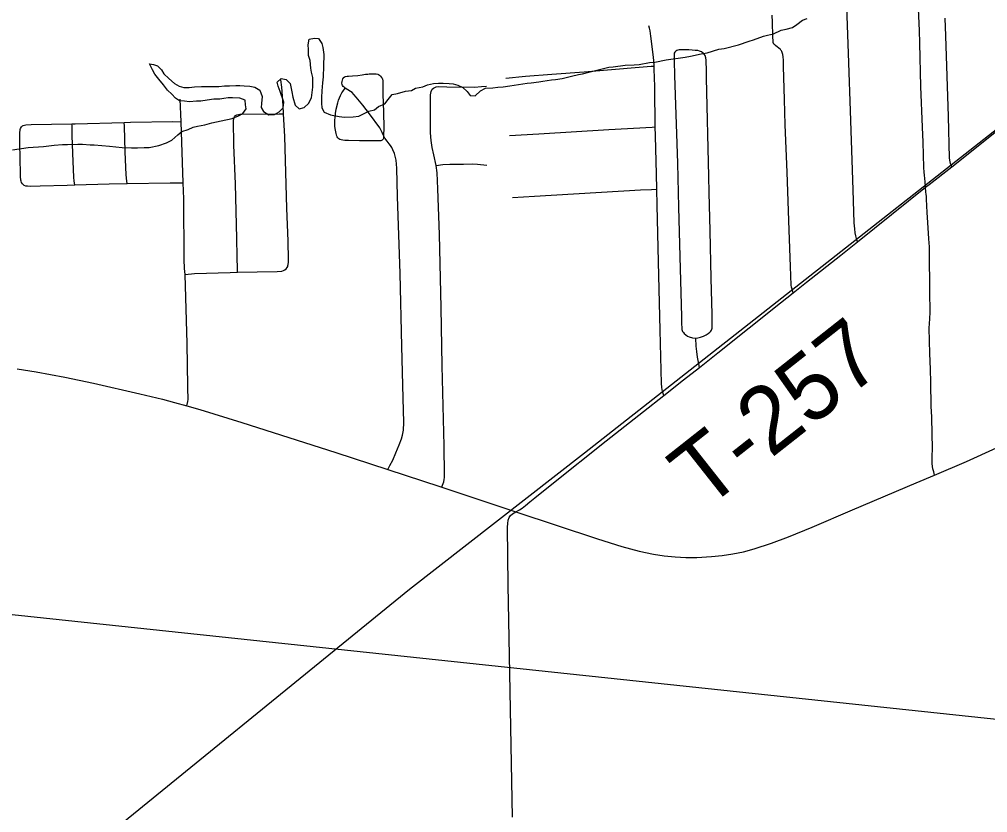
# Model space of a CAD drawing. Extents: x 63.4 to 97.4, y 0.4 to 22.4.
# Drawn here: x 71.177 to 72.001, y 17.297 to 17.973 of the extents above; entities that cross this region are included whole.
import ezdxf

# ---------------------------------------------------------------- set-up
doc = ezdxf.new("R2010")
doc.units = 0
for name, color, linetype in [('GM_X_Minor_River', 7, 'Continuous'), ('GM_X_Rail_Line', 7, 'Continuous'), ('GM_X_State_Route', 7, 'Continuous'), ('GM_X_Township_Road', 7, 'Continuous'), ('GM_X_Township_Road_Text', 7, 'Continuous'), ('SH_Data', 7, 'Continuous')]:
    doc.layers.add(name, color=color, linetype=linetype)

msp = doc.modelspace()

# ---------------------------------------------------------------- linework, layer by layer
at = {"layer": 'GM_X_Minor_River'}
for points in [[(71.42284, 17.94762), (71.42245, 17.95142), (71.42318, 17.95636), (71.42773, 17.95714), (71.43115, 17.95678), (71.43421, 17.95261), (71.43499, 17.94919), (71.43578, 17.94312), (71.43545, 17.93323), (71.43512, 17.92411), (71.43476, 17.91916), (71.43403, 17.91232), (71.43368, 17.90662), (71.43371, 17.90167), (71.43411, 17.89787), (71.43602, 17.89408), (71.44135, 17.89183), (71.44895, 17.89034), (71.45351, 17.88998), (71.46072, 17.89001), (71.46566, 17.8908), (71.46907, 17.89233), (71.47399, 17.89501), (71.47892, 17.89618), (71.48232, 17.89886), (71.48763, 17.90116), (71.49064, 17.90498), (71.49404, 17.90917), (71.49859, 17.90995), (71.50541, 17.91189), (71.51035, 17.91267), (71.51375, 17.91459), (71.5202, 17.91576), (71.52399, 17.91729), (71.5293, 17.91846), (71.53348, 17.91886), (71.53727, 17.91887), (71.54259, 17.91852), (71.54601, 17.91815), (71.54981, 17.91703), (71.554, 17.91515), (71.55781, 17.91175), (71.56049, 17.90834), (71.56466, 17.90798), (71.5692, 17.91218), (71.57336, 17.91448), (71.57982, 17.91489), (71.58399, 17.91529), (71.58854, 17.91569), (71.59423, 17.91648), (71.60144, 17.91765), (71.60903, 17.91882), (71.61245, 17.91922), (71.6189, 17.92001), (71.62231, 17.92041), (71.62952, 17.92158), (71.63293, 17.92198), (71.63863, 17.92276), (71.64659, 17.9247), (71.65266, 17.92625), (71.65607, 17.92664), (71.66138, 17.92819), (71.67048, 17.93051), (71.67844, 17.93245), (71.68224, 17.93284), (71.69248, 17.93403), (71.70007, 17.93445), (71.70425, 17.93485), (71.71297, 17.93641), (71.71753, 17.93681), (71.72739, 17.93876), (71.74332, 17.94111), (71.74788, 17.94189), (71.75698, 17.94383), (71.76229, 17.94462), (71.77214, 17.9477), (71.7767, 17.94848), (71.78883, 17.95158), (71.79793, 17.95466), (71.80172, 17.95582), (71.81006, 17.9589), (71.81347, 17.95968), (71.81878, 17.96084), (71.82522, 17.96391), (71.82939, 17.96469), (71.8347, 17.96624), (71.83848, 17.96892), (71.8434, 17.97236), (71.84719, 17.9739)], [(71.19698, 17.86485), (71.20609, 17.86603), (71.2133, 17.86645), (71.21747, 17.86647), (71.2262, 17.86689), (71.23038, 17.86691), (71.23684, 17.86618), (71.24026, 17.86619), (71.24671, 17.86584), (71.25317, 17.86511), (71.26419, 17.86402), (71.27216, 17.86368), (71.2771, 17.8637), (71.28279, 17.86411), (71.28696, 17.86412), (71.29531, 17.86569), (71.30175, 17.868), (71.3063, 17.8703), (71.31159, 17.87488), (71.31499, 17.87756), (71.3203, 17.87948), (71.32447, 17.8814), (71.32826, 17.88218), (71.33433, 17.88335), (71.34039, 17.8849), (71.34836, 17.88684), (71.35784, 17.88878), (71.36314, 17.89109), (71.36693, 17.893), (71.36957, 17.89682), (71.36917, 17.90023), (71.36877, 17.90442), (71.36421, 17.90591), (71.35813, 17.90627), (71.35434, 17.90625), (71.35054, 17.90585), (71.34713, 17.90508), (71.34219, 17.90505), (71.3365, 17.90426), (71.33119, 17.90348), (71.32739, 17.90346), (71.32132, 17.90305), (71.31714, 17.90342), (71.31296, 17.90378), (71.30953, 17.90604), (71.30648, 17.90945), (71.30266, 17.91285), (71.29923, 17.9174), (71.29541, 17.92232), (71.29197, 17.92649), (71.29005, 17.93028), (71.28737, 17.93521), (71.29078, 17.93485), (71.29421, 17.93372), (71.29764, 17.93032), (71.29956, 17.92691), (71.30375, 17.92274), (71.30871, 17.91858), (71.31252, 17.91632), (71.3167, 17.9152), (71.32126, 17.91522), (71.32581, 17.91562), (71.3315, 17.91603), (71.34631, 17.9161), (71.35124, 17.9165), (71.35542, 17.91652), (71.36073, 17.91692), (71.36415, 17.91694), (71.36795, 17.91658), (71.37289, 17.91622), (71.37707, 17.91548), (71.38126, 17.91284), (71.38318, 17.90752), (71.38284, 17.90144), (71.38247, 17.89802), (71.38439, 17.8946), (71.38896, 17.89196), (71.39389, 17.89199), (71.39768, 17.89428), (71.40108, 17.89772), (71.40181, 17.90267), (71.39873, 17.91177), (71.39681, 17.91633), (71.39603, 17.91975), (71.39943, 17.9228), (71.40361, 17.92206), (71.40705, 17.91866), (71.4086, 17.91144), (71.40938, 17.90688), (71.41132, 17.90005), (71.41475, 17.89702), (71.41892, 17.89818), (71.4227, 17.90162), (71.42533, 17.90619), (71.42643, 17.91532), (71.42638, 17.92369), (71.42522, 17.92824), (71.42483, 17.93166), (71.42403, 17.93812), (71.42287, 17.9423), (71.42284, 17.94762)], [(71.1708, 17.86207), (71.18408, 17.86403), (71.19698, 17.86485)]]:
    msp.add_lwpolyline(points, dxfattribs=at)
at = {"layer": 'GM_X_Rail_Line'}
msp.add_lwpolyline([(65.50725, 16.09139), (66.11906, 16.08304), (66.42387, 16.07871), (66.83132, 16.06881), (67.54296, 16.06263), (67.97019, 16.05768), (68.6101, 16.24632), (69.10534, 16.39723), (70.19289, 16.73926), (70.26462, 16.75905), (70.36416, 16.76338), (70.58983, 16.77637), (70.68566, 16.83018), (70.78273, 16.89883), (71.21738, 17.25013), (71.50859, 17.48763), (71.6576, 17.60391), (72.12996, 17.97501), (72.30725, 18.11599)], dxfattribs=at)
at = {"layer": 'GM_X_State_Route'}
msp.add_lwpolyline([(71.17472, 17.67544), (71.19078, 17.67288), (71.21527, 17.66831), (71.23963, 17.66319), (71.27908, 17.65424), (71.29834, 17.64946), (71.30876, 17.64669), (71.31903, 17.64381), (71.33022, 17.64066), (71.3659, 17.62965), (71.44591, 17.60413), (71.49015, 17.58964), (71.53458, 17.57508), (71.53615, 17.57456), (71.59939, 17.55369), (71.66866, 17.53048), (71.6894, 17.52401), (71.70437, 17.52002), (71.71648, 17.5175), (71.72565, 17.51615), (71.73488, 17.51522), (71.74413, 17.51476), (71.7534, 17.51476), (71.76576, 17.51541), (71.775, 17.51636), (71.78417, 17.51775), (71.79324, 17.5196), (71.80219, 17.52199), (71.81689, 17.52687), (71.83142, 17.53227), (71.85151, 17.54054), (71.88581, 17.55516), (71.94013, 17.57817), (71.95588, 17.5849), (71.98298, 17.59647), (72.00842, 17.60799)], dxfattribs=at)
at = {"layer": 'GM_X_Township_Road'}
for p, q in [((71.31434, 17.88584), (71.31351, 17.90527)), ((71.31614, 17.8338), (71.31434, 17.88584)), ((71.89023, 17.78372), (71.94815, 17.83008))]:
    msp.add_line(p, q, dxfattribs=at)
for points in [[(71.89023, 17.78372), (71.88938, 17.78646), (71.88868, 17.78877), (71.88814, 17.79143), (71.88779, 17.79463), (71.88745, 17.79985), (71.8865, 17.82784), (71.88427, 17.89529), (71.88271, 17.93602), (71.88116, 17.98417), (71.88108, 17.98638)], [(71.94815, 17.83008), (71.94786, 17.83484), (71.94751, 17.8376), (71.94717, 17.84029), (71.94689, 17.84285), (71.94676, 17.84685), (71.94613, 17.86854), (71.94558, 17.88132), (71.94412, 17.91592), (71.94315, 17.95294), (71.94293, 17.96373), (71.9422, 17.98219), (71.94214, 17.98396), (71.94192, 17.98539), (71.94159, 17.986)], [(71.83529, 17.74004), (71.83444, 17.74326), (71.834, 17.74494), (71.8337, 17.74679), (71.83302, 17.76251), (71.83195, 17.79356), (71.83019, 17.84299), (71.82869, 17.8832), (71.82802, 17.90486), (71.82724, 17.93293), (71.82706, 17.93834), (71.82675, 17.94123), (71.82647, 17.94318), (71.82628, 17.94404), (71.82599, 17.94494), (71.82571, 17.9457), (71.82535, 17.94646), (71.82491, 17.94707), (71.82448, 17.94756), (71.82307, 17.94872), (71.82174, 17.9497), (71.82067, 17.95049), (71.81967, 17.95135), (71.81906, 17.952), (71.81868, 17.95265), (71.81842, 17.9535), (71.81828, 17.95475), (71.8181, 17.95812), (71.81801, 17.96229), (71.81783, 17.96726), (71.8178, 17.97067), (71.81757, 17.97666)], [(71.97038, 17.84767), (71.96945, 17.85048), (71.96904, 17.85171), (71.9688, 17.85317), (71.96863, 17.8552), (71.96765, 17.89055), (71.96651, 17.9249), (71.96541, 17.95904), (71.96477, 17.9743)], [(71.71709, 17.93342), (71.71673, 17.93801), (71.7162, 17.94332), (71.71425, 17.95876), (71.71354, 17.9633), (71.71302, 17.96578), (71.71239, 17.96781)], [(71.76391, 17.82555), (71.76357, 17.83937), (71.76158, 17.92332), (71.76149, 17.93172), (71.76141, 17.93588), (71.76125, 17.93829), (71.76099, 17.94045), (71.76041, 17.94244), (71.75966, 17.94353), (71.75875, 17.94445), (71.75725, 17.94553), (71.75575, 17.94619), (71.75426, 17.94652), (71.75209, 17.94677), (71.74939, 17.94699), (71.7465, 17.94714), (71.74353, 17.94727), (71.74062, 17.94727), (71.7384, 17.94729), (71.73723, 17.94704), (71.73637, 17.94668), (71.73541, 17.94602), (71.73469, 17.94532), (71.73422, 17.94427), (71.73405, 17.94253), (71.73405, 17.94036), (71.73405, 17.93795), (71.73447, 17.92523), (71.73687, 17.85059), (71.73775, 17.8133), (71.73922, 17.76048), (71.74024, 17.72006), (71.74031, 17.71382), (71.74048, 17.71041), (71.74073, 17.70892), (71.74131, 17.70733), (71.74189, 17.70642), (71.74264, 17.70542), (71.74388, 17.70434), (71.74547, 17.70334), (71.74697, 17.70268), (71.74963, 17.70193), (71.75253, 17.7016)], [(71.59064, 17.92306), (71.60749, 17.92475), (71.62979, 17.92662), (71.65736, 17.9285), (71.67745, 17.93004), (71.70757, 17.93276), (71.71455, 17.93327), (71.71709, 17.93342)], [(71.71789, 17.88152), (71.71753, 17.91494), (71.71738, 17.92459), (71.71717, 17.92961), (71.71709, 17.93342)], [(71.45389, 17.91462), (71.45298, 17.91535), (71.45229, 17.91602), (71.45179, 17.91679), (71.45144, 17.91775), (71.45125, 17.91889), (71.45129, 17.92012), (71.45156, 17.92139), (71.45203, 17.92255), (71.45269, 17.92354), (71.45322, 17.92402), (71.45382, 17.92439), (71.45554, 17.92476), (71.45678, 17.9249), (71.46029, 17.9251), (71.46475, 17.92543), (71.46841, 17.92595), (71.47129, 17.92638), (71.47318, 17.92659), (71.47447, 17.92672), (71.47794, 17.92688), (71.47904, 17.92688), (71.48034, 17.92679), (71.48169, 17.92652), (71.48247, 17.92615), (71.48326, 17.92566), (71.48409, 17.92482), (71.48492, 17.9237), (71.48535, 17.92298), (71.48569, 17.92216), (71.486, 17.92085), (71.48609, 17.91902), (71.48599, 17.91574), (71.48596, 17.90949), (71.48649, 17.89402), (71.48679, 17.88072), (71.48659, 17.87412)], [(71.4014, 17.89276), (71.40111, 17.89984), (71.39999, 17.91545), (71.39924, 17.92165)], [(71.52791, 17.91366), (71.52913, 17.91465), (71.53031, 17.91515), (71.53149, 17.91556), (71.53323, 17.91592), (71.54059, 17.91579), (71.56399, 17.91543), (71.57002, 17.91584), (71.57434, 17.91633)], [(71.48659, 17.87412), (71.48659, 17.87242), (71.48648, 17.87172), (71.4862, 17.87102), (71.4854, 17.87032), (71.4842, 17.86981), (71.48167, 17.86966), (71.46626, 17.86976), (71.45686, 17.86983), (71.45377, 17.87002), (71.45205, 17.8702), (71.45049, 17.87051), (71.44943, 17.87089), (71.44849, 17.87151), (71.44776, 17.87219), (71.44719, 17.87301), (71.44685, 17.87377), (71.44649, 17.87481), (71.4462, 17.87591), (71.44594, 17.87733), (71.44551, 17.88027), (71.44529, 17.88226), (71.44511, 17.88466), (71.44519, 17.88701), (71.44541, 17.88991), (71.44578, 17.89301), (71.44639, 17.89661), (71.44769, 17.90212), (71.44835, 17.90427), (71.44909, 17.90632), (71.44985, 17.90817), (71.45042, 17.90936), (71.45113, 17.91062), (71.45184, 17.91182), (71.45389, 17.91462)], [(71.48659, 17.87412), (71.48559, 17.87677), (71.48443, 17.87905), (71.48339, 17.88062), (71.47459, 17.89272), (71.46899, 17.90012), (71.46339, 17.90701), (71.46144, 17.90918), (71.45978, 17.91076), (71.45839, 17.91172), (71.45618, 17.91322), (71.45389, 17.91462)], [(71.53135, 17.84864), (71.52933, 17.85771), (71.52808, 17.86389), (71.52716, 17.87006), (71.52662, 17.87641), (71.52662, 17.88566), (71.52673, 17.90885), (71.52678, 17.91039), (71.5271, 17.91175), (71.52791, 17.91366)], [(71.3623, 17.7577), (71.36225, 17.76002), (71.36205, 17.77115), (71.36166, 17.78644), (71.36046, 17.83292), (71.35926, 17.8659), (71.35901, 17.88709), (71.35911, 17.88835), (71.35939, 17.88942), (71.3597, 17.89022), (71.36053, 17.89126)], [(71.36053, 17.89126), (71.36178, 17.89193), (71.36305, 17.89222), (71.3644, 17.89239), (71.36592, 17.89243), (71.39779, 17.89272), (71.4014, 17.89276)], [(71.40377, 17.76062), (71.40455, 17.76163), (71.405, 17.76258), (71.40526, 17.76347), (71.40547, 17.76441), (71.40567, 17.76638), (71.40573, 17.76867), (71.40552, 17.78433), (71.40436, 17.81241), (71.40257, 17.87345), (71.4014, 17.89276)], [(71.17825, 17.88153), (71.17924, 17.88236), (71.17984, 17.88263), (71.18091, 17.88303), (71.18194, 17.88327), (71.18673, 17.88346), (71.22136, 17.88404)], [(71.22136, 17.88404), (71.2242, 17.88409), (71.26591, 17.88533)], [(71.22392, 17.83221), (71.22331, 17.83518), (71.223, 17.83863), (71.22228, 17.852), (71.22157, 17.87404), (71.22139, 17.88236), (71.22136, 17.88404)], [(71.26591, 17.88533), (71.27118, 17.88549), (71.30709, 17.88611), (71.31434, 17.88584)], [(71.26844, 17.83324), (71.26817, 17.83536), (71.26751, 17.8406), (71.26653, 17.86024), (71.26598, 17.88232), (71.26591, 17.88533)], [(71.17924, 17.83292), (71.17844, 17.8343), (71.17807, 17.83528), (71.17787, 17.83627), (71.17751, 17.83933), (71.17738, 17.84336), (71.17733, 17.85304), (71.17698, 17.86935), (71.17698, 17.87542), (71.17707, 17.87717), (71.17715, 17.87836), (71.17726, 17.87931), (71.1775, 17.88026), (71.17825, 17.88153)], [(71.49015, 17.58964), (71.49202, 17.59304), (71.49445, 17.59747), (71.49723, 17.6039), (71.5, 17.61066), (71.50188, 17.61586), (71.50287, 17.61897), (71.50365, 17.62307), (71.50398, 17.62961), (71.5032, 17.65056), (71.5022, 17.69467), (71.50076, 17.75651), (71.49864, 17.82223), (71.49802, 17.84629), (71.49774, 17.84975), (71.49746, 17.85307), (71.49663, 17.85654), (71.4959, 17.85881), (71.4946, 17.86201), (71.49365, 17.86391), (71.49247, 17.86582), (71.4914, 17.86722), (71.48962, 17.8694), (71.48777, 17.872), (71.48659, 17.87412)], [(71.594, 17.87423), (71.61899, 17.87567), (71.67834, 17.87925), (71.71524, 17.88136), (71.71789, 17.88152)], [(71.71931, 17.82839), (71.71916, 17.84136), (71.71815, 17.87401), (71.71789, 17.88152)], [(71.97038, 17.84767), (72.00132, 17.87218), (72.01155, 17.88036)], [(71.53135, 17.84864), (71.53715, 17.84938), (71.54295, 17.84992), (71.55475, 17.84993), (71.56273, 17.85005), (71.56672, 17.84993), (71.57452, 17.84902)], [(71.53615, 17.57456), (71.53681, 17.57631), (71.53783, 17.57901), (71.53829, 17.58111), (71.53845, 17.58281), (71.53855, 17.58521), (71.53826, 17.60984), (71.53658, 17.6781), (71.53563, 17.72774), (71.53433, 17.78981), (71.53298, 17.82888), (71.53215, 17.84249), (71.53135, 17.84864)], [(71.94815, 17.83008), (71.95124, 17.83251), (71.97038, 17.84767)], [(71.17924, 17.83292), (71.18041, 17.83196), (71.18171, 17.83146), (71.18335, 17.83128), (71.18618, 17.83118), (71.1943, 17.83136), (71.21723, 17.83205), (71.22392, 17.83221)], [(71.22392, 17.83221), (71.25297, 17.83292), (71.26844, 17.83324)], [(71.26844, 17.83324), (71.30484, 17.83397), (71.31614, 17.8338)], [(71.31773, 17.75575), (71.3172, 17.76097), (71.3169, 17.76856), (71.31661, 17.82031), (71.31614, 17.8338)], [(71.59646, 17.82145), (71.61514, 17.82248), (71.70542, 17.82805), (71.71477, 17.82827), (71.71931, 17.82839)], [(71.72527, 17.65275), (71.72444, 17.65533), (71.72385, 17.65755), (71.72349, 17.6599), (71.72332, 17.6628), (71.72206, 17.7085), (71.72073, 17.76667), (71.71967, 17.81498), (71.71931, 17.82839)], [(71.75253, 17.7016), (71.75437, 17.70184), (71.75661, 17.70235), (71.75901, 17.70324), (71.76126, 17.70432), (71.76316, 17.70565), (71.76446, 17.70662), (71.76535, 17.7075), (71.76597, 17.70842), (71.76626, 17.70916), (71.76638, 17.70998), (71.76657, 17.7118), (71.76657, 17.71404), (71.76649, 17.71637), (71.76633, 17.72165), (71.76566, 17.75275), (71.7647, 17.79297), (71.76391, 17.82555)], [(71.95588, 17.5849), (71.95503, 17.58776), (71.95434, 17.59009), (71.95391, 17.59233), (71.95378, 17.59482), (71.95383, 17.60002), (71.95391, 17.60796), (71.95382, 17.61979), (71.95339, 17.63412), (71.95296, 17.6437), (71.95252, 17.6639), (71.95226, 17.67504), (71.95166, 17.68834), (71.9514, 17.69913), (71.95131, 17.7101), (71.95165, 17.71804), (71.95191, 17.72373), (71.95183, 17.74134), (71.95148, 17.7751), (71.95139, 17.77933), (71.95113, 17.78279), (71.95096, 17.78615), (71.95014, 17.80023), (71.94959, 17.80866), (71.94904, 17.81998), (71.94883, 17.82227), (71.94862, 17.8242), (71.94842, 17.82586), (71.94815, 17.83008)], [(71.83529, 17.74004), (71.8468, 17.74932), (71.87596, 17.7723), (71.89023, 17.78372)], [(71.3623, 17.7577), (71.3791, 17.758), (71.39602, 17.75843), (71.39997, 17.75877), (71.40159, 17.75923), (71.40261, 17.75967), (71.40377, 17.76062)], [(71.31773, 17.75575), (71.32567, 17.7566), (71.35593, 17.75758), (71.3623, 17.7577)], [(71.31903, 17.64381), (71.31993, 17.64758), (71.32014, 17.64938), (71.32021, 17.65103), (71.32017, 17.65253), (71.3201, 17.65608), (71.32007, 17.66029), (71.3193, 17.6971), (71.31773, 17.75575)], [(71.75556, 17.67666), (71.7713, 17.68906), (71.79804, 17.71041), (71.82474, 17.73153), (71.83529, 17.74004)], [(71.75556, 17.67666), (71.75495, 17.67981), (71.75445, 17.68238), (71.75395, 17.68546), (71.75329, 17.69021), (71.75287, 17.69478), (71.75253, 17.7016)], [(71.72527, 17.65275), (71.74199, 17.66598), (71.75556, 17.67666)], [(71.59939, 17.55369), (71.60233, 17.55534), (71.60467, 17.55672), (71.60747, 17.55883), (71.61132, 17.562), (71.61534, 17.56541), (71.62986, 17.57717), (71.6761, 17.61393), (71.70784, 17.63896), (71.72527, 17.65275)], [(71.59642, 17.29342), (71.59417, 17.41568), (71.59274, 17.49112), (71.5923, 17.54064), (71.59238, 17.54375), (71.59282, 17.5466), (71.59359, 17.54876), (71.59463, 17.55032), (71.59645, 17.55188), (71.59939, 17.55369)]]:
    msp.add_lwpolyline(points, dxfattribs=at)
at = {"layer": 'SH_Data'}
msp.add_lwpolyline([(69.50164, 17.64339), (73.23413, 16.75633), (73.23413, 17.24633)], close=True, dxfattribs=at)

# ---------------------------------------------------------------- texts
at = {"layer": 'GM_X_Township_Road_Text'}
msp.add_text('T-257', height=0.056818, rotation=38.2672, dxfattribs=at).set_placement((71.76006, 17.55432))

doc.saveas('drawing.dxf')
